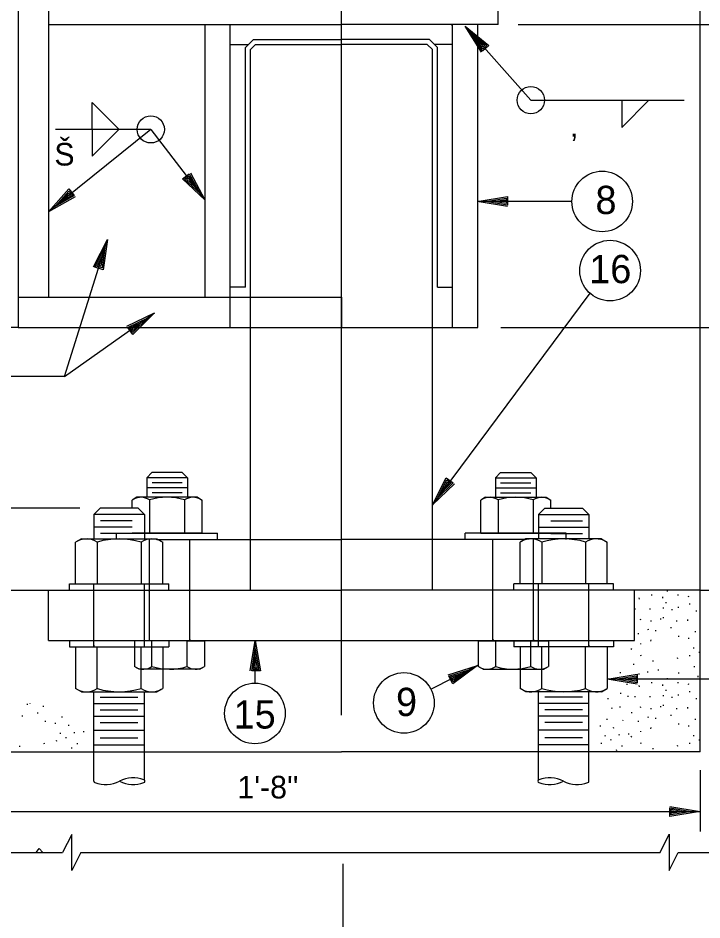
# Model space of a CAD drawing. Extents: x -0.2 to 13.5, y -0.2 to 9.5.
# Drawn here: x 7.276 to 8.686, y 3.159 to 5.019 of the extents above; entities that cross this region are included whole.
import ezdxf

# ---------------------------------------------------------------- set-up
doc = ezdxf.new("R2010")
doc.units = 0
for name, color, linetype in [('Level 10', 7, 'Continuous'), ('Level 13', 7, 'Continuous'), ('Level 2', 7, 'Continuous'), ('Level 3', 7, 'Continuous'), ('Level 4', 7, 'Continuous'), ('Level 50', 7, 'Continuous')]:
    doc.layers.add(name, color=color, linetype=linetype)

msp = doc.modelspace()

# ---------------------------------------------------------------- linework, layer by layer
at = {"layer": 'Level 10'}
for points in [[(7.3132, 3.2981), (7.3195, 3.3064)], [(7.3195, 3.3064), (7.3269, 3.2981)]]:
    msp.add_lwpolyline(points, dxfattribs=at)
at = {"layer": 'Level 13'}
for points in [[(7.4049, 3.298), (7.3863, 3.2605), (7.3863, 3.3354), (7.3675, 3.298)], [(8.5995, 3.298), (8.6182, 3.3355), (8.6182, 3.2606), (8.6369, 3.298)]]:
    msp.add_lwpolyline(points, dxfattribs=at)
at = {"layer": 'Level 2'}
for p, q in [((7.2758, 5.9367), (7.2758, 4.3808)), ((8.6821, 3.5058), (8.6821, 5.9367)), ((7.9425, 3.5815), (7.9425, 5.6922)), ((7.3383, 5.6308), (7.3383, 4.4433)), ((8.2654, 5.0058), (8.2654, 5.0683)), ((7.3383, 5.0058), (7.9425, 5.0058)), ((7.6612, 4.4433), (7.6612, 5.0058)), ((7.7133, 4.3808), (7.7133, 5.0058)), ((8.2654, 5.0058), (7.9425, 5.0058)), ((8.1716, 4.3808), (8.1716, 5.0058)), ((8.2237, 4.3808), (8.2237, 5.0058)), ((7.7611, 4.9746), (7.7446, 4.9581)), ((7.7611, 4.9746), (7.9425, 4.9746)), ((8.1239, 4.9746), (7.9425, 4.9746)), ((8.1239, 4.9746), (8.1404, 4.9581)), ((7.7133, 4.9642), (7.7507, 4.9642)), ((7.7446, 4.4642), (7.7446, 4.9581)), ((7.7654, 4.9642), (7.755, 4.9538)), ((7.755, 4.3808), (7.755, 4.9538)), ((7.7654, 4.9642), (7.9425, 4.9642)), ((8.1196, 4.9642), (7.9425, 4.9642)), ((8.1196, 4.9642), (8.13, 4.9538)), ((8.13, 4.3808), (8.13, 4.9538)), ((8.1716, 4.9642), (8.1343, 4.9642)), ((8.1404, 4.4642), (8.1404, 4.9581)), ((7.7446, 4.4642), (7.7133, 4.4642)), ((8.1404, 4.4642), (8.1716, 4.4642)), ((7.2758, 4.4433), (7.9425, 4.4433)), ((7.9425, 4.4433), (7.9425, 4.3808)), ((7.2758, 4.3808), (8.2237, 4.3808)), ((7.755, 3.9433), (7.755, 4.3808)), ((8.13, 3.9433), (8.13, 4.3808)), ((7.5411, 4.071), (7.5516, 4.0814)), ((7.6143, 4.0814), (7.5516, 4.0814)), ((7.6248, 4.071), (7.6143, 4.0814)), ((8.2601, 4.071), (8.2706, 4.0814)), ((8.2706, 4.0814), (8.3333, 4.0814)), ((8.3438, 4.071), (8.3333, 4.0814)), ((7.5411, 4.071), (7.5411, 4.0305)), ((7.6248, 4.071), (7.5411, 4.071)), ((7.6142, 4.0605), (7.552, 4.0605)), ((7.6248, 4.071), (7.6248, 4.0305)), ((8.2601, 4.071), (8.3438, 4.071)), ((8.2601, 4.071), (8.2601, 4.0305)), ((8.2707, 4.0605), (8.3329, 4.0605)), ((8.3438, 4.071), (8.3438, 4.0305)), ((7.6248, 4.05), (7.5411, 4.05)), ((7.6142, 4.0396), (7.552, 4.0396)), ((8.2601, 4.05), (8.3438, 4.05)), ((8.2707, 4.0396), (8.3329, 4.0396)), ((7.5204, 4.0305), (7.5108, 4.0249)), ((7.5108, 4.0081), (7.5108, 4.0249)), ((7.6455, 4.0305), (7.5204, 4.0305)), ((7.5468, 4.0251), (7.5468, 3.9564)), ((7.6192, 4.0251), (7.6192, 3.9564)), ((7.6455, 4.0305), (7.6552, 4.0249)), ((7.6552, 3.9564), (7.6552, 4.0249)), ((8.2394, 4.0305), (8.2297, 4.0249)), ((8.2297, 3.9564), (8.2297, 4.0249)), ((8.2394, 4.0305), (8.3645, 4.0305)), ((8.2658, 4.0251), (8.2658, 3.9564)), ((8.3381, 4.0251), (8.3381, 3.9564)), ((8.3645, 4.0305), (8.3742, 4.0249)), ((8.3742, 4.0081), (8.3742, 4.0249)), ((7.432, 3.995), (7.445, 4.0081)), ((7.5233, 4.0081), (7.445, 4.0081)), ((7.5363, 3.995), (7.5233, 4.0081)), ((8.3486, 3.995), (8.3617, 4.0081)), ((8.3617, 4.0081), (8.4399, 4.0081)), ((8.453, 3.995), (8.4399, 4.0081)), ((7.432, 3.995), (7.432, 3.9446)), ((7.5363, 3.995), (7.432, 3.995)), ((7.5108, 3.982), (7.4455, 3.982)), ((7.5363, 3.995), (7.5363, 3.9446)), ((8.3486, 3.995), (8.453, 3.995)), ((8.3486, 3.995), (8.3486, 3.9446)), ((8.3742, 3.982), (8.4394, 3.982)), ((8.453, 3.995), (8.453, 3.9446)), ((7.5108, 3.969), (7.432, 3.969)), ((8.3486, 3.969), (8.453, 3.969)), ((7.4062, 3.9446), (7.3941, 3.9377)), ((7.4062, 3.9446), (7.5621, 3.9446)), ((7.5108, 3.956), (7.4455, 3.956)), ((7.4788, 3.9433), (7.4788, 3.9564)), ((7.4788, 3.9564), (7.6872, 3.9564)), ((7.6552, 3.9564), (7.5108, 3.9564)), ((7.5621, 3.9446), (7.5741, 3.9377)), ((7.6187, 3.9564), (7.6552, 3.9564)), ((7.6872, 3.9433), (7.6872, 3.9564)), ((8.1978, 3.9433), (8.1978, 3.9564)), ((8.4061, 3.9564), (8.1978, 3.9564)), ((8.2297, 3.9564), (8.3742, 3.9564)), ((8.2663, 3.9564), (8.2297, 3.9564)), ((8.3228, 3.9446), (8.3108, 3.9377)), ((8.4788, 3.9446), (8.3228, 3.9446)), ((8.3742, 3.956), (8.4394, 3.956)), ((8.4061, 3.9433), (8.4061, 3.9564)), ((8.4788, 3.9446), (8.4908, 3.9377)), ((7.3941, 3.8522), (7.3941, 3.9377)), ((7.4391, 3.9378), (7.4391, 3.8522)), ((7.5292, 3.9378), (7.5292, 3.8522)), ((7.5465, 3.735), (7.5465, 3.9433)), ((7.5617, 3.9433), (7.9425, 3.9433)), ((7.5741, 3.8522), (7.5741, 3.9377)), ((7.6301, 3.735), (7.6301, 3.9433)), ((7.755, 3.8392), (7.755, 3.9433)), ((8.3233, 3.9433), (7.9425, 3.9433)), ((8.13, 3.8392), (8.13, 3.9433)), ((8.2548, 3.735), (8.2548, 3.9433)), ((8.3108, 3.8522), (8.3108, 3.9377)), ((8.3385, 3.735), (8.3385, 3.9433)), ((8.3557, 3.9378), (8.3557, 3.8522)), ((8.4459, 3.9378), (8.4459, 3.8522)), ((8.4908, 3.8522), (8.4908, 3.9377)), ((7.3815, 3.8392), (7.3815, 3.8522)), ((7.3815, 3.8522), (7.5867, 3.8522)), ((7.432, 3.722), (7.432, 3.8522)), ((7.5363, 3.722), (7.5363, 3.8522)), ((7.5867, 3.8392), (7.5867, 3.8522)), ((8.5034, 3.8522), (8.2982, 3.8522)), ((8.2982, 3.8392), (8.2982, 3.8522)), ((8.3487, 3.722), (8.3487, 3.8522)), ((8.4529, 3.8489), (8.4529, 3.8522)), ((8.4529, 3.722), (8.4529, 3.8522)), ((8.5034, 3.8392), (8.5034, 3.8522)), ((7.0154, 3.8392), (7.5465, 3.8392)), ((7.3383, 3.735), (7.3383, 3.8392)), ((7.5461, 3.8368), (7.5461, 3.8394)), ((7.5465, 3.8392), (7.9425, 3.8392)), ((8.6821, 3.8392), (7.9425, 3.8392)), ((8.3389, 3.8368), (8.3389, 3.8394)), ((8.5466, 3.735), (8.5466, 3.8392)), ((8.6821, 3.8392), (9.0154, 3.8392)), ((7.3383, 3.735), (8.5466, 3.735)), ((7.3815, 3.735), (7.3815, 3.722)), ((7.3815, 3.722), (7.5867, 3.722)), ((7.3941, 3.722), (7.3941, 3.6365)), ((7.432, 3.7253), (7.432, 3.722)), ((7.4391, 3.6363), (7.4391, 3.722)), ((7.6601, 3.7347), (7.5157, 3.7347)), ((7.5157, 3.7347), (7.5157, 3.6818)), ((7.5292, 3.6363), (7.5292, 3.722)), ((7.5461, 3.7374), (7.5461, 3.7347)), ((7.5517, 3.6816), (7.5517, 3.7347)), ((7.5741, 3.722), (7.5741, 3.6365)), ((7.5867, 3.735), (7.5867, 3.722)), ((7.6236, 3.7347), (7.6601, 3.7347)), ((7.6241, 3.6816), (7.6241, 3.7347)), ((7.6297, 3.7374), (7.6297, 3.7347)), ((7.6601, 3.7347), (7.6601, 3.6818)), ((8.2248, 3.7347), (8.3693, 3.7347)), ((8.2614, 3.7347), (8.2248, 3.7347)), ((8.2248, 3.7347), (8.2248, 3.6818)), ((8.2552, 3.7374), (8.2552, 3.7347)), ((8.2609, 3.6816), (8.2609, 3.7347)), ((8.2982, 3.735), (8.2982, 3.722)), ((8.5034, 3.722), (8.2982, 3.722)), ((8.3108, 3.722), (8.3108, 3.6365)), ((8.3332, 3.6816), (8.3332, 3.7347)), ((8.3389, 3.7374), (8.3389, 3.7347)), ((8.3557, 3.6363), (8.3557, 3.722)), ((8.3693, 3.7347), (8.3693, 3.6818)), ((8.4459, 3.6363), (8.4459, 3.722)), ((8.4529, 3.7253), (8.4529, 3.722)), ((8.4908, 3.722), (8.4908, 3.6365)), ((8.5034, 3.735), (8.5034, 3.722)), ((7.5254, 3.6762), (7.5157, 3.6818)), ((7.6504, 3.6762), (7.5254, 3.6762)), ((7.6504, 3.6762), (7.6601, 3.6818)), ((8.2345, 3.6762), (8.2248, 3.6818)), ((8.2345, 3.6762), (8.3596, 3.6762)), ((8.3596, 3.6762), (8.3693, 3.6818)), ((7.4062, 3.6295), (7.3941, 3.6365)), ((7.4062, 3.6295), (7.5621, 3.6295)), ((7.432, 3.445), (7.432, 3.6295)), ((7.5363, 3.4475), (7.5363, 3.6295)), ((7.5621, 3.6295), (7.5741, 3.6365)), ((8.3228, 3.6295), (8.3108, 3.6365)), ((8.4788, 3.6295), (8.3228, 3.6295)), ((8.3486, 3.4475), (8.3486, 3.6295)), ((8.4529, 3.445), (8.4529, 3.6295)), ((8.4788, 3.6295), (8.4908, 3.6365)), ((7.4452, 3.6182), (7.5227, 3.6182)), ((8.4398, 3.6182), (8.3622, 3.6182)), ((7.432, 3.6052), (7.5363, 3.6052)), ((7.4452, 3.5922), (7.5227, 3.5922)), ((8.4529, 3.6052), (8.3486, 3.6052)), ((8.4398, 3.5922), (8.3622, 3.5922)), ((7.432, 3.5791), (7.5363, 3.5791)), ((8.4529, 3.5791), (8.3486, 3.5791)), ((7.4452, 3.5661), (7.5227, 3.5661)), ((8.4398, 3.5661), (8.3622, 3.5661)), ((7.432, 3.5502), (7.5363, 3.5502)), ((8.4529, 3.5502), (8.3486, 3.5502)), ((7.432, 3.5202), (7.5363, 3.5202)), ((7.4452, 3.5343), (7.5227, 3.5343)), ((8.4529, 3.5202), (8.3486, 3.5202)), ((8.4398, 3.5343), (8.3622, 3.5343)), ((7.0154, 3.5058), (7.9425, 3.5058)), ((8.6821, 3.5058), (7.9425, 3.5058)), ((6.9074, 3.298), (7.3675, 3.298)), ((7.4049, 3.298), (8.5995, 3.298)), ((8.6369, 3.298), (9.4234, 3.298))]:
    msp.add_line(p, q, dxfattribs=at)
for points in [[(8.1716, 5.0028), (8.1686, 5.0058)], [(8.2237, 5.0041), (8.222, 5.0058)], [(7.9642, 4.9746), (7.9633, 4.9755)]]:
    msp.add_lwpolyline(points, dxfattribs=at)
for centre, radius, start, end in [((7.529, 3.9992), 0.0314, 55.489, 120.2876), ((7.5834, 3.9051), 0.1255, 73.5034, 106.9816), ((7.6369, 3.9992), 0.0314, 59.7124, 124.511), ((8.248, 3.9992), 0.0314, 55.489, 120.2876), ((8.3015, 3.9051), 0.1255, 73.0184, 106.4966), ((8.3559, 3.9992), 0.0314, 59.7124, 124.511), ((7.4169, 3.9056), 0.0391, 55.489, 120.2876), ((7.4836, 3.7883), 0.1564, 73.0184, 106.4966), ((7.5514, 3.9056), 0.0391, 59.7124, 124.511), ((8.3335, 3.9056), 0.0391, 55.489, 120.2876), ((8.4014, 3.7883), 0.1564, 73.5034, 106.9816), ((8.468, 3.9056), 0.0391, 59.7124, 124.511), ((7.5339, 3.7075), 0.0314, 239.7124, 304.511), ((7.5884, 3.8016), 0.1255, 253.0184, 286.4966), ((7.6418, 3.7075), 0.0314, 235.489, 300.2876), ((8.2431, 3.7075), 0.0314, 239.7124, 304.511), ((8.2966, 3.8016), 0.1255, 253.5034, 286.9816), ((8.351, 3.7075), 0.0314, 235.489, 300.2876), ((7.4169, 3.6685), 0.0391, 239.7124, 304.511), ((7.4836, 3.7859), 0.1564, 253.5034, 286.9816), ((7.5514, 3.6685), 0.0391, 235.489, 300.2876), ((8.3335, 3.6685), 0.0391, 239.7124, 304.511), ((8.4014, 3.7859), 0.1564, 253.0184, 286.4966), ((8.468, 3.6685), 0.0391, 235.489, 300.2876), ((7.4352, 3.445), 0.00313, 180, 249.6845), ((7.4561, 3.5019), 0.0638, 249.8081, 296.6071), ((7.5133, 3.388), 0.0638, 69.8064, 116.6071), ((7.5133, 3.5019), 0.0638, 243.3929, 290.1936), ((7.5342, 3.445), 0.00313, 290.1936, 69.8064), ((8.3507, 3.445), 0.00313, 110.1936, 249.8064), ((8.3717, 3.388), 0.0638, 63.3929, 110.1936), ((8.3717, 3.5019), 0.0638, 249.8064, 296.6071), ((8.4288, 3.5019), 0.0638, 243.3929, 290.1919), ((8.4498, 3.445), 0.00313, 290.3155, 0)]:
    msp.add_arc(centre, radius, start, end, dxfattribs=at)
at = {"layer": 'Level 3'}
for p, q in [((8.3068, 5.0058), (8.9685, 5.0058)), ((8.333, 4.8497), (8.1978, 5.0025)), ((8.1978, 5.0025), (8.1978, 5.0025)), ((8.2092, 4.9895), (8.2092, 4.9895)), ((7.5493, 4.7894), (7.3386, 4.6193)), ((7.5493, 4.7894), (7.6609, 4.6439)), ((7.6504, 4.6577), (7.6504, 4.6577)), ((7.6609, 4.6439), (7.6609, 4.6439)), ((8.4177, 4.6407), (8.2223, 4.6407)), ((8.2223, 4.6407), (8.2223, 4.6407)), ((8.2397, 4.6407), (8.2397, 4.6407)), ((7.3386, 4.6193), (7.3386, 4.6193)), ((7.3521, 4.6302), (7.3521, 4.6302)), ((7.3716, 4.2795), (7.4598, 4.5625)), ((7.4598, 4.5625), (7.4598, 4.5625)), ((7.4547, 4.546), (7.4547, 4.546)), ((8.4546, 4.4517), (8.13, 4.0148)), ((7.3716, 4.2795), (7.5572, 4.4108)), ((7.5572, 4.4108), (7.5572, 4.4108)), ((7.543, 4.4008), (7.543, 4.4008)), ((7.2758, 4.3808), (6.5258, 4.3808)), ((8.2709, 4.3808), (8.9699, 4.3808)), ((7.3716, 4.2795), (6.9867, 4.2795)), ((7.4031, 4.0081), (7.0918, 4.0081)), ((8.6151, 3.836), (8.6149, 3.838)), ((8.5571, 3.8206), (8.5564, 3.8231)), ((8.5829, 3.8278), (8.5827, 3.8299)), ((8.6056, 3.8226), (8.6056, 3.8251)), ((8.6123, 3.8122), (8.6121, 3.8142)), ((8.6368, 3.8278), (8.6366, 3.8299)), ((8.6583, 3.8255), (8.6586, 3.8274)), ((8.5482, 3.7993), (8.548, 3.8013)), ((8.5794, 3.7993), (8.5793, 3.8013)), ((8.6066, 3.8013), (8.6064, 3.8034)), ((8.6246, 3.7979), (8.6244, 3.8)), ((8.6375, 3.8027), (8.6373, 3.8047)), ((8.6613, 3.8095), (8.6611, 3.8115)), ((8.6749, 3.7952), (8.6747, 3.7973)), ((8.5596, 3.7774), (8.5589, 3.7792)), ((8.6012, 3.7782), (8.601, 3.7803)), ((8.6066, 3.7811), (8.6066, 3.7834)), ((8.6567, 3.7757), (8.6567, 3.7782)), ((8.5754, 3.7565), (8.5752, 3.7585)), ((8.5815, 3.7741), (8.5813, 3.7762)), ((8.6225, 3.7606), (8.6224, 3.7626)), ((8.6341, 3.7741), (8.6339, 3.7762)), ((8.555, 3.7483), (8.5548, 3.7504)), ((8.591, 3.7544), (8.5908, 3.7565)), ((8.6381, 3.7429), (8.638, 3.7449)), ((8.6592, 3.7388), (8.6591, 3.7409)), ((8.6728, 3.7524), (8.6726, 3.7544)), ((7.7649, 3.6473), (7.7649, 3.7352)), ((7.7649, 3.7352), (7.7649, 3.7352)), ((8.5597, 3.7273), (8.5596, 3.7293)), ((8.5806, 3.7339), (8.5809, 3.7364)), ((8.6691, 3.7187), (8.6693, 3.7206)), ((7.7649, 3.7179), (7.7649, 3.7179)), ((8.5399, 3.7166), (8.5412, 3.7187)), ((8.5604, 3.7028), (8.5602, 3.7048)), ((8.6613, 3.7028), (8.6611, 3.7048)), ((8.6809, 3.7096), (8.6808, 3.7116)), ((8.1272, 3.6348), (8.2229, 3.6834)), ((8.2229, 3.6834), (8.2229, 3.6834)), ((8.5455, 3.6851), (8.5453, 3.6871)), ((8.5856, 3.6919), (8.5854, 3.6939)), ((8.6365, 3.6971), (8.6354, 3.6994)), ((8.2075, 3.6756), (8.2075, 3.6756)), ((8.5183, 3.6681), (8.5181, 3.6701)), ((8.5564, 3.6654), (8.5562, 3.6674)), ((8.5747, 3.6695), (8.5745, 3.6715)), ((8.5964, 3.6735), (8.5963, 3.6756)), ((8.6381, 3.6674), (8.638, 3.6695)), ((8.6708, 3.6803), (8.6706, 3.6824)), ((8.855, 3.6555), (8.4904, 3.6555)), ((8.4904, 3.6555), (8.4904, 3.6555)), ((8.5077, 3.6555), (8.5077, 3.6555)), ((8.5359, 3.6586), (8.5358, 3.6606)), ((8.5829, 3.647), (8.5827, 3.6491)), ((8.6151, 3.6552), (8.6149, 3.6572)), ((8.6368, 3.647), (8.6366, 3.6491)), ((8.6583, 3.6447), (8.6586, 3.6466)), ((8.6782, 3.6599), (8.6781, 3.662)), ((8.5319, 3.6436), (8.5317, 3.6457)), ((8.5571, 3.6398), (8.5564, 3.6423)), ((8.6056, 3.6418), (8.6056, 3.6443)), ((8.6123, 3.6314), (8.6121, 3.6334)), ((8.6613, 3.6287), (8.6611, 3.6307)), ((8.4925, 3.6144), (8.4923, 3.6165)), ((8.519, 3.6253), (8.5188, 3.6274)), ((8.5339, 3.6192), (8.5337, 3.6212)), ((8.5482, 3.6185), (8.548, 3.6205)), ((8.5794, 3.6185), (8.5793, 3.6205)), ((8.6066, 3.6205), (8.6064, 3.6226)), ((8.6246, 3.6171), (8.6244, 3.6192)), ((8.6375, 3.6219), (8.6373, 3.6239)), ((8.6749, 3.6144), (8.6747, 3.6165)), ((7.2952, 3.6025), (7.295, 3.6045)), ((7.328, 3.5984), (7.3279, 3.6004)), ((8.5006, 3.594), (8.5004, 3.5961)), ((8.5176, 3.5968), (8.5174, 3.5988)), ((8.5596, 3.5966), (8.5589, 3.5984)), ((8.5815, 3.5934), (8.5813, 3.5954)), ((8.6012, 3.5974), (8.601, 3.5995)), ((8.6066, 3.6003), (8.6066, 3.6026)), ((8.6341, 3.5934), (8.6339, 3.5954)), ((8.6567, 3.5949), (8.6567, 3.5974)), ((7.285, 3.5787), (7.2848, 3.5807)), ((7.3165, 3.5848), (7.3163, 3.5869)), ((7.3668, 3.5767), (7.3666, 3.5787)), ((8.4904, 3.5716), (8.4903, 3.5736)), ((8.5227, 3.5699), (8.5236, 3.5719)), ((8.5414, 3.5852), (8.5412, 3.5872)), ((8.5754, 3.5757), (8.5752, 3.5777)), ((8.591, 3.5736), (8.5908, 3.5757)), ((8.6225, 3.5798), (8.6224, 3.5818)), ((8.6728, 3.5716), (8.6726, 3.5736)), ((7.3321, 3.5672), (7.332, 3.5692)), ((7.3532, 3.5631), (7.353, 3.5651)), ((7.3804, 3.559), (7.3802, 3.561)), ((8.4769, 3.558), (8.4767, 3.5601)), ((8.504, 3.5539), (8.5039, 3.556)), ((8.555, 3.5675), (8.5548, 3.5696)), ((8.5806, 3.5531), (8.5809, 3.5556)), ((8.6381, 3.5621), (8.638, 3.5641)), ((8.6592, 3.558), (8.6591, 3.5601)), ((7.3631, 3.543), (7.3633, 3.5448)), ((7.3749, 3.5338), (7.3748, 3.5359)), ((7.3919, 3.544), (7.3918, 3.5461)), ((7.4116, 3.5461), (7.4115, 3.5481)), ((8.4867, 3.5379), (8.4869, 3.5398)), ((8.5156, 3.539), (8.5154, 3.541)), ((8.5353, 3.541), (8.5351, 3.5431)), ((8.5399, 3.5359), (8.5412, 3.5379)), ((8.5597, 3.5465), (8.5596, 3.5485)), ((8.6691, 3.5379), (8.6693, 3.5398)), ((7.2795, 3.5162), (7.2794, 3.5182)), ((7.3305, 3.5214), (7.3293, 3.5236)), ((7.3553, 3.527), (7.3551, 3.5291)), ((7.398, 3.5216), (7.3979, 3.5236)), ((8.4789, 3.522), (8.4787, 3.524)), ((8.4986, 3.5288), (8.4984, 3.5308)), ((8.5217, 3.5165), (8.5215, 3.5186)), ((8.5604, 3.522), (8.5602, 3.524)), ((8.6365, 3.5164), (8.6354, 3.5186)), ((8.6613, 3.522), (8.6611, 3.524)), ((8.6809, 3.5288), (8.6808, 3.5308)), ((7.3865, 3.5127), (7.3863, 3.5148)), ((8.5101, 3.5077), (8.51, 3.5097)), ((8.5856, 3.5111), (8.5854, 3.5131)), ((8.6821, 3.4678), (8.6821, 3.341)), ((7.0154, 3.3827), (8.6821, 3.3827)), ((8.6647, 3.3827), (8.6647, 3.3827)), ((8.6821, 3.3827), (8.6821, 3.3827)), ((7.9456, 3.2749), (7.9456, 3.1029))]:
    msp.add_line(p, q, dxfattribs=at)
for points in [[(8.2313, 4.9489), (8.1978, 5.0025), (8.2468, 4.9626), (8.2336, 4.9509), (8.2092, 4.9895), (8.2425, 4.9624), (8.2341, 4.9549), (8.2203, 4.977), (8.2383, 4.9622), (8.2348, 4.9591), (8.2318, 4.964)], [(7.6312, 4.6997), (7.6609, 4.6439), (7.6148, 4.6871), (7.6288, 4.6979), (7.6504, 4.6577), (7.6191, 4.687), (7.628, 4.6939), (7.6402, 4.6709), (7.6233, 4.6869), (7.627, 4.6898), (7.6297, 4.6847)], [(7.3936, 4.6504), (7.3386, 4.6193), (7.3806, 4.6665), (7.3917, 4.6528), (7.3521, 4.6302), (7.3806, 4.6622), (7.3877, 4.6534), (7.365, 4.6407), (7.3806, 4.658), (7.3836, 4.6543), (7.3785, 4.6516)], [(8.2847, 4.6303), (8.2223, 4.6407), (8.2847, 4.651), (8.2847, 4.6333), (8.2397, 4.6407), (8.282, 4.6477), (8.282, 4.6363), (8.2563, 4.6407), (8.2793, 4.6443), (8.2793, 4.6397), (8.2737, 4.6407)], [(7.4314, 4.5061), (7.4598, 4.5625), (7.4511, 4.4999), (7.4343, 4.5052), (7.4547, 4.546), (7.4488, 4.5035), (7.4379, 4.5069), (7.4497, 4.5301), (7.4464, 4.507), (7.4419, 4.5084), (7.4446, 4.5135)], [(7.5003, 4.3832), (7.5572, 4.4108), (7.5123, 4.3664), (7.5021, 4.3808), (7.543, 4.4008), (7.5125, 4.3706), (7.506, 4.3799), (7.5294, 4.3912), (7.5128, 4.3749), (7.5101, 4.3787), (7.5153, 4.3812)], [(7.7546, 3.6729), (7.7649, 3.7352), (7.7753, 3.6729), (7.7576, 3.6729), (7.7649, 3.7179), (7.7719, 3.6755), (7.7606, 3.6755), (7.7649, 3.7012), (7.7686, 3.6782), (7.7639, 3.6782), (7.7649, 3.6839)], [(8.1627, 3.6644), (8.2229, 3.6834), (8.172, 3.646), (8.164, 3.6617), (8.2075, 3.6756), (8.1729, 3.6502), (8.1678, 3.6603), (8.1926, 3.668), (8.1738, 3.6543), (8.1716, 3.6585), (8.1772, 3.6602)], [(8.5527, 3.6452), (8.4904, 3.6555), (8.5527, 3.6658), (8.5527, 3.6482), (8.5077, 3.6555), (8.55, 3.6625), (8.55, 3.6512), (8.5244, 3.6555), (8.5474, 3.6592), (8.5474, 3.6545), (8.5417, 3.6555)], [(7.3006, 3.6054), (7.3006, 3.6061)], [(7.3647, 3.5051), (7.3646, 3.5066)], [(8.5454, 3.505), (8.5453, 3.5064)], [(8.6197, 3.393), (8.6821, 3.3827), (8.6197, 3.3723), (8.6197, 3.39), (8.6647, 3.3827), (8.6224, 3.3757), (8.6224, 3.387), (8.6481, 3.3827), (8.6251, 3.379), (8.6251, 3.3837), (8.6307, 3.3827)]]:
    msp.add_lwpolyline(points, dxfattribs=at)
for centre in [(8.4802, 4.6407), (8.4965, 4.4981), (8.0714, 3.6064), (7.7642, 3.5848)]:
    msp.add_circle(centre, 0.0625, dxfattribs=at)
at = {"layer": 'Level 4'}
for p, q in [((7.4283, 4.8451), (7.4842, 4.7892)), ((7.4283, 4.7888), (7.4283, 4.8451)), ((8.333, 4.8497), (8.6491, 4.8497)), ((8.5205, 4.8497), (8.5205, 4.7934)), ((8.5205, 4.7934), (8.5764, 4.8493)), ((7.5493, 4.7894), (7.353, 4.7894)), ((7.4283, 4.79), (7.4283, 4.7338)), ((7.4283, 4.7338), (7.4842, 4.7896))]:
    msp.add_line(p, q, dxfattribs=at)
for centre in [(8.333, 4.8497), (7.5493, 4.7894)]:
    msp.add_circle(centre, 0.0281, dxfattribs=at)
at = {"layer": 'Level 50'}
for p, q in [((8.1403, 4.0287), (8.1403, 4.0287)), ((8.13, 4.0148), (8.13, 4.0148))]:
    msp.add_line(p, q, dxfattribs=at)
msp.add_lwpolyline([(8.1754, 4.0586), (8.13, 4.0148), (8.1588, 4.071), (8.173, 4.0604), (8.1403, 4.0287), (8.1599, 4.0668), (8.169, 4.0601), (8.1503, 4.0421), (8.161, 4.0627), (8.1648, 4.0599), (8.1606, 4.056)], dxfattribs=at)

# ---------------------------------------------------------------- texts
at = {"layer": 'Level 3'}
for s, height, p in [('Š', 0.0467, (7.3505, 4.7148)), ('‚', 0.0467, (8.4155, 4.7741)), ('8', 0.0583, (8.4664, 4.6147)), ('16', 0.05833, (8.4535, 4.4722)), ('9', 0.0583, (8.0551, 3.5794)), ('15', 0.05833, (7.7202, 3.5536)), ("1'-8''", 0.04667, (7.7281, 3.4094))]:
    msp.add_text(s, height=height, dxfattribs=at).set_placement(p)

doc.saveas('drawing.dxf')
